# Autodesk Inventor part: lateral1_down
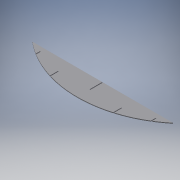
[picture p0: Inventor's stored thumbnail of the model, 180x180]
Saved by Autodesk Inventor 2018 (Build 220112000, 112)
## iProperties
Created: 2019-03
Part Number: lateral1_down
Material: Generic
Document SubType Name: Modeling
Designer: vpimentel
Density: 1 g/cm^3
Appearance: Default
Author: vpimentel
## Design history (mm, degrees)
sketch "Sketch1"
  geometry: L1 (0, 39.111)-(-2.9, 39.111) reference; L2 (-2.9, 39.111)-(-2.9, 94.108) reference; L3 (-2.9, 94.108)-(-276.45, 94.108) reference; L4 (-208.7, 42.199)-(-208.7, 68.451) reference; L5 (-208.7, 68.451)-(-205.8, 68.451) reference; L6 (-205.8, 68.451)-(-205.8, 40.451) reference; L7 (-115.8, 0.856)-(-115.8, 47) reference; L8 (-115.8, 47)-(-112.9, 47) reference; L9 (-112.9, 47)-(-112.9, 0) reference; L10 (110, 0)-(110, 47) reference; L11 (110, 47)-(112.9, 47) reference; L12 (112.9, 47)-(112.9, 0.856) reference; L13 (202.9, 40.451)-(202.9, 68.451) reference; L14 (202.9, 68.451)-(205.8, 68.451) reference; L15 (205.8, 68.451)-(205.8, 42.199) reference; L16 (273.55, 94.108)-(0, 94.108) reference; L17 (0, 94.108)-(0, 39.111) reference; L18 (-1.45, 94.108)-(-1.45, 4.108); L19 (-2.9, 49.108)-(0, 49.108); L20 (0, 49.108)-(0, 94.108); L21 (-2.9, 94.108)-(-2.9, 49.108); L22 (112.9, 21.147)-(112.9, 49.108); L23 (112.9, 49.108)-(110, 49.108); L24 (110, 49.108)-(110, 20.276); L25 (205.8, 63.335)-(205.8, 78.548); L26 (205.8, 78.548)-(202.9, 78.548); L27 (202.9, 78.548)-(202.9, 61.548); L28 (-115.8, 21.147)-(-115.8, 49.108); L29 (-115.8, 49.108)-(-112.9, 49.108); L30 (-112.9, 49.108)-(-112.9, 20.276); L31 (-208.7, 63.335)-(-208.7, 78.548); L32 (-208.7, 78.548)-(-205.8, 78.548); L33 (-205.8, 78.548)-(-205.8, 61.548); L34 (248.55, 94.108)-(0, 94.108); L35 (-2.9, 94.108)-(-251.45, 94.108); A1 r 398.75 centre (-1.45, 382.858) between (-276.45, 94.108) and (-208.7, 42.199) reference; A2 r 398.75 centre (-1.45, 382.858) between (-205.8, 40.451) and (-115.8, 0.856) reference; A3 r 398.75 centre (-1.45, 382.858) between (-112.9, 0) and (-1.45, -15.892) reference; A4 r 123.752 centre (-0.95, 107.859) between (-1.45, -15.892) and (0, -15.889) reference; A5 r 398.75 centre (-1.45, 382.858) between (0, -15.889) and (110, 0) reference; A6 r 398.75 centre (-1.45, 382.858) between (112.9, 0.856) and (202.9, 40.451) reference; A7 r 398.75 centre (-1.45, 382.858) between (205.8, 42.199) and (273.55, 94.108) reference; A8 r 392.222 centre (-1.45, 396.33) between (-251.45, 94.108) and (-208.7, 63.335); A9 r 392.222 centre (-1.45, 396.33) between (-205.8, 61.548) and (-115.8, 21.147); A10 r 392.222 centre (-1.45, 396.33) between (-112.9, 20.276) and (110, 20.276); A11 r 392.222 centre (-1.45, 396.33) between (112.9, 21.147) and (202.9, 61.548); A12 r 392.222 centre (-1.45, 396.33) between (205.8, 63.335) and (248.55, 94.108); 3 further points
  constraints: 36 end point, 11 point on circle, 9 point on line, 5 centre point, 5 parallel, 4 vertical alignment, 3 horizontal, 3 horizontal alignment, 2 midpoint, 1 perpendicular, 1 vertical
  dimensions: "d1" = 500 distance of L34.start L35.end; "d2" = 90 distance of L18.start L18.end; "d3" = 45 distance of L21.start L19.start; "d5" = 17 distance of L26.end L27.end; "d6" = 2.9 distance between parallel lines of L7 L30 (derived)
extrude "Extrusion1" new body sketch "Sketch1" distance "d7" = 2.9 (= d6); taper "d8" = 0 deg
body "Solid1"
node "Reference1"
